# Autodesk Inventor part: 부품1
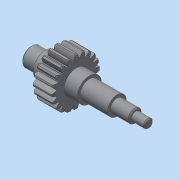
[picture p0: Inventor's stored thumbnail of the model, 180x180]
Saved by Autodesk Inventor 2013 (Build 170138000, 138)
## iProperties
Created: 2019-12
Part Number: 부품1
Material: 일반
Document SubType Name: Modeling
Designer: dgall
Density: 1 g/cm^3
Mass: 35.4008 g
Surface Area: 133.579 cm^2
Volume: 35.4008 cm^3
Author: dgall
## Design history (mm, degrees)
sketch "스케치1"
  geometry: L1 (-9, 0)-(-9, 11); L2 (-9, 11)-(-19, 11); L3 (-19, 11)-(-19, 8.5); L4 (-19, 8.5)-(-32, 8.5); L5 (-32, 8.5)-(-32, 0); L6 (9, 0)-(9, 11); L7 (9, 11)-(21, 11); L8 (21, 11)-(21, 8.5); L9 (21, 8.5)-(46, 8.5); L10 (46, 8.5)-(46, 6); L11 (46, 6)-(63, 6); L12 (63, 6)-(63, 0); L13 (-32, 0)-(-9, 0); L14 (9, 0)-(63, 0); L15 (63, 0)-(63, 4); L16 (63, 4)-(75, 4); L17 (75, 4)-(75, 0); L18 (63, 0)-(75, 0); L19 (63, 0)-(63, 6); 1 further point
  constraints: 38 end point, 6 parallel, 5 perpendicular, 2 collinear, 1 point on line
  dimensions: "d0" = 9 distance of point (0, 0) L1.start; "d1" = 11 distance of L1.start L1.end; "d2" = 10 distance of L1.end L2.end; "d3" = 2.5 distance of L2.end L3.end; "d4" = 13 distance of L3.end L4.end; "d5" = 9 distance of point (0, 0) L6.start; "d6" = 11 distance of L6.start L6.end; "d7" = 12 distance of L6.end L7.end; "d8" = 2.5 distance of L7.end L8.end; "d9" = 25 distance of L8.end L9.end; "d10" = 2.5 distance of L9.end L10.end; "d12" = 6 distance of L11.end L12.end; "d34" = 4 distance of L12.end L15.end; "d35" = 12 distance of L15.end L16.end; "d37" = 6 distance of L12.end L11.end (derived)
revolve "회전1" sketch "스케치1" stored, may be unused: angle "d13" = 90 deg
sketch "스케치2"
  geometry: C1 r 11 at (0, 0) reference; C2 r 17.5 at (0, 0)
  constraints: 1 centre point, 1 coincident
  dimensions: "d14" = 35 diameter of C2
extrude "돌출1" join sketch "스케치2" distance "d15" = 18; taper "d16" = 0 deg
sketch "스케치3"
  geometry: C1 r 17.5 at (0, 0) reference; A1 r 22 centre (0, 0) between (0.75, 21.987) and (-0.75, 21.987); A2 r 17.5 centre (0, 0) between (2.241, 17.356) and (-2.241, 17.356); A3 r 9.388 centre (7.136, 16.892) between (-0.75, 21.987) and (-2.241, 17.356); A4 r 9.388 centre (-7.136, 16.892) between (2.241, 17.356) and (0.75, 21.987)
  constraints: 8 point on circle, 4 centre point, 2 coincident
  dimensions: "d17" = 44 diameter of A1; "d18" = 35 diameter of A2
extrude "돌출2" join sketch "스케치3" stored distance "d20" = 18; taper "d21" = 0 deg
chamfer "모따기1" distance "d22" = 1; stored, may be unused: second distance "d23" = 2, angle "d24" = 45 deg
fillet "모깎기1" dims "d25" = 0.2
node "작업 평면1"
sketch "스케치5"
  geometry: 1 further point
node "작업 평면2"
node "작업 평면3"
chamfer "모따기2" distance "d45" = 1; stored, may be unused: second distance "d46" = 2, angle "d47" = 45 deg
node "작업 평면4"
sketch "스케치7"
  geometry: L1 (-46, 8.5)-(-46, -8.5) reference; L2 (-57, 2)-(-51, 2); L3 (-57, -2)-(-51, -2); L4 (-55, 0)-(-57, 0); A1 r 2 centre (-51, 0) between (-51, -2) and (-51, 2); A2 r 2 centre (-57, 0) between (-57, 2) and (-57, -2); 1 further point
  constraints: 6 end point, 5 point on circle, 4 tangent, 2 centre point, 1 coincident
  dimensions: "d59" = 6 distance of A1.centre L4.end; "d60" = 4 diameter of A2
extrude "돌출4" cut sketch "스케치7" distance "d61" = 2.5; taper "d62" = 0 deg
node "솔리드1"
pattern_circular "원형 패턴1" dims "d27" = 360 deg
other parameters: "d29" = 8.5, "d36" = 6, "d38" = 6, "d56" = 6
